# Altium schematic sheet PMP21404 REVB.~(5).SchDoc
size 431 x 279 mm; Date: Not shown in title block; ApprovedBy: Not shown in title block; CheckedBy: Not shown in title block; Author: Not shown in title block; CompanyName: Not shown in title block; Engineer: Not shown in title block; Organization: Not shown in title block; Address1: Not shown in title block; Address2: Not shown in title block; Address3: Not shown in title block; Address4: Not shown in title block; DocumentNumber: 1; Revision: Use project parameter SCH_Rev; SheetNumber: 1; SheetTotal: 1; PageSetup: Record=PageOptions¦CenterHorizontal=True¦CenterVertical=True¦PrintScale=1.00¦XCorrection=1.00¦YCorrection=1.00¦PrintKind=0¦BorderSize=5000000¦LeftOffset=0¦BottomOffset=0¦Orientation=2¦PaperLength=1000¦PaperWidth=1000¦Scale=100¦PaperSource=15¦PrintQuality=600¦MediaType=1¦DitherType=10¦PaperKind=Letter¦PrintScaleMode=1
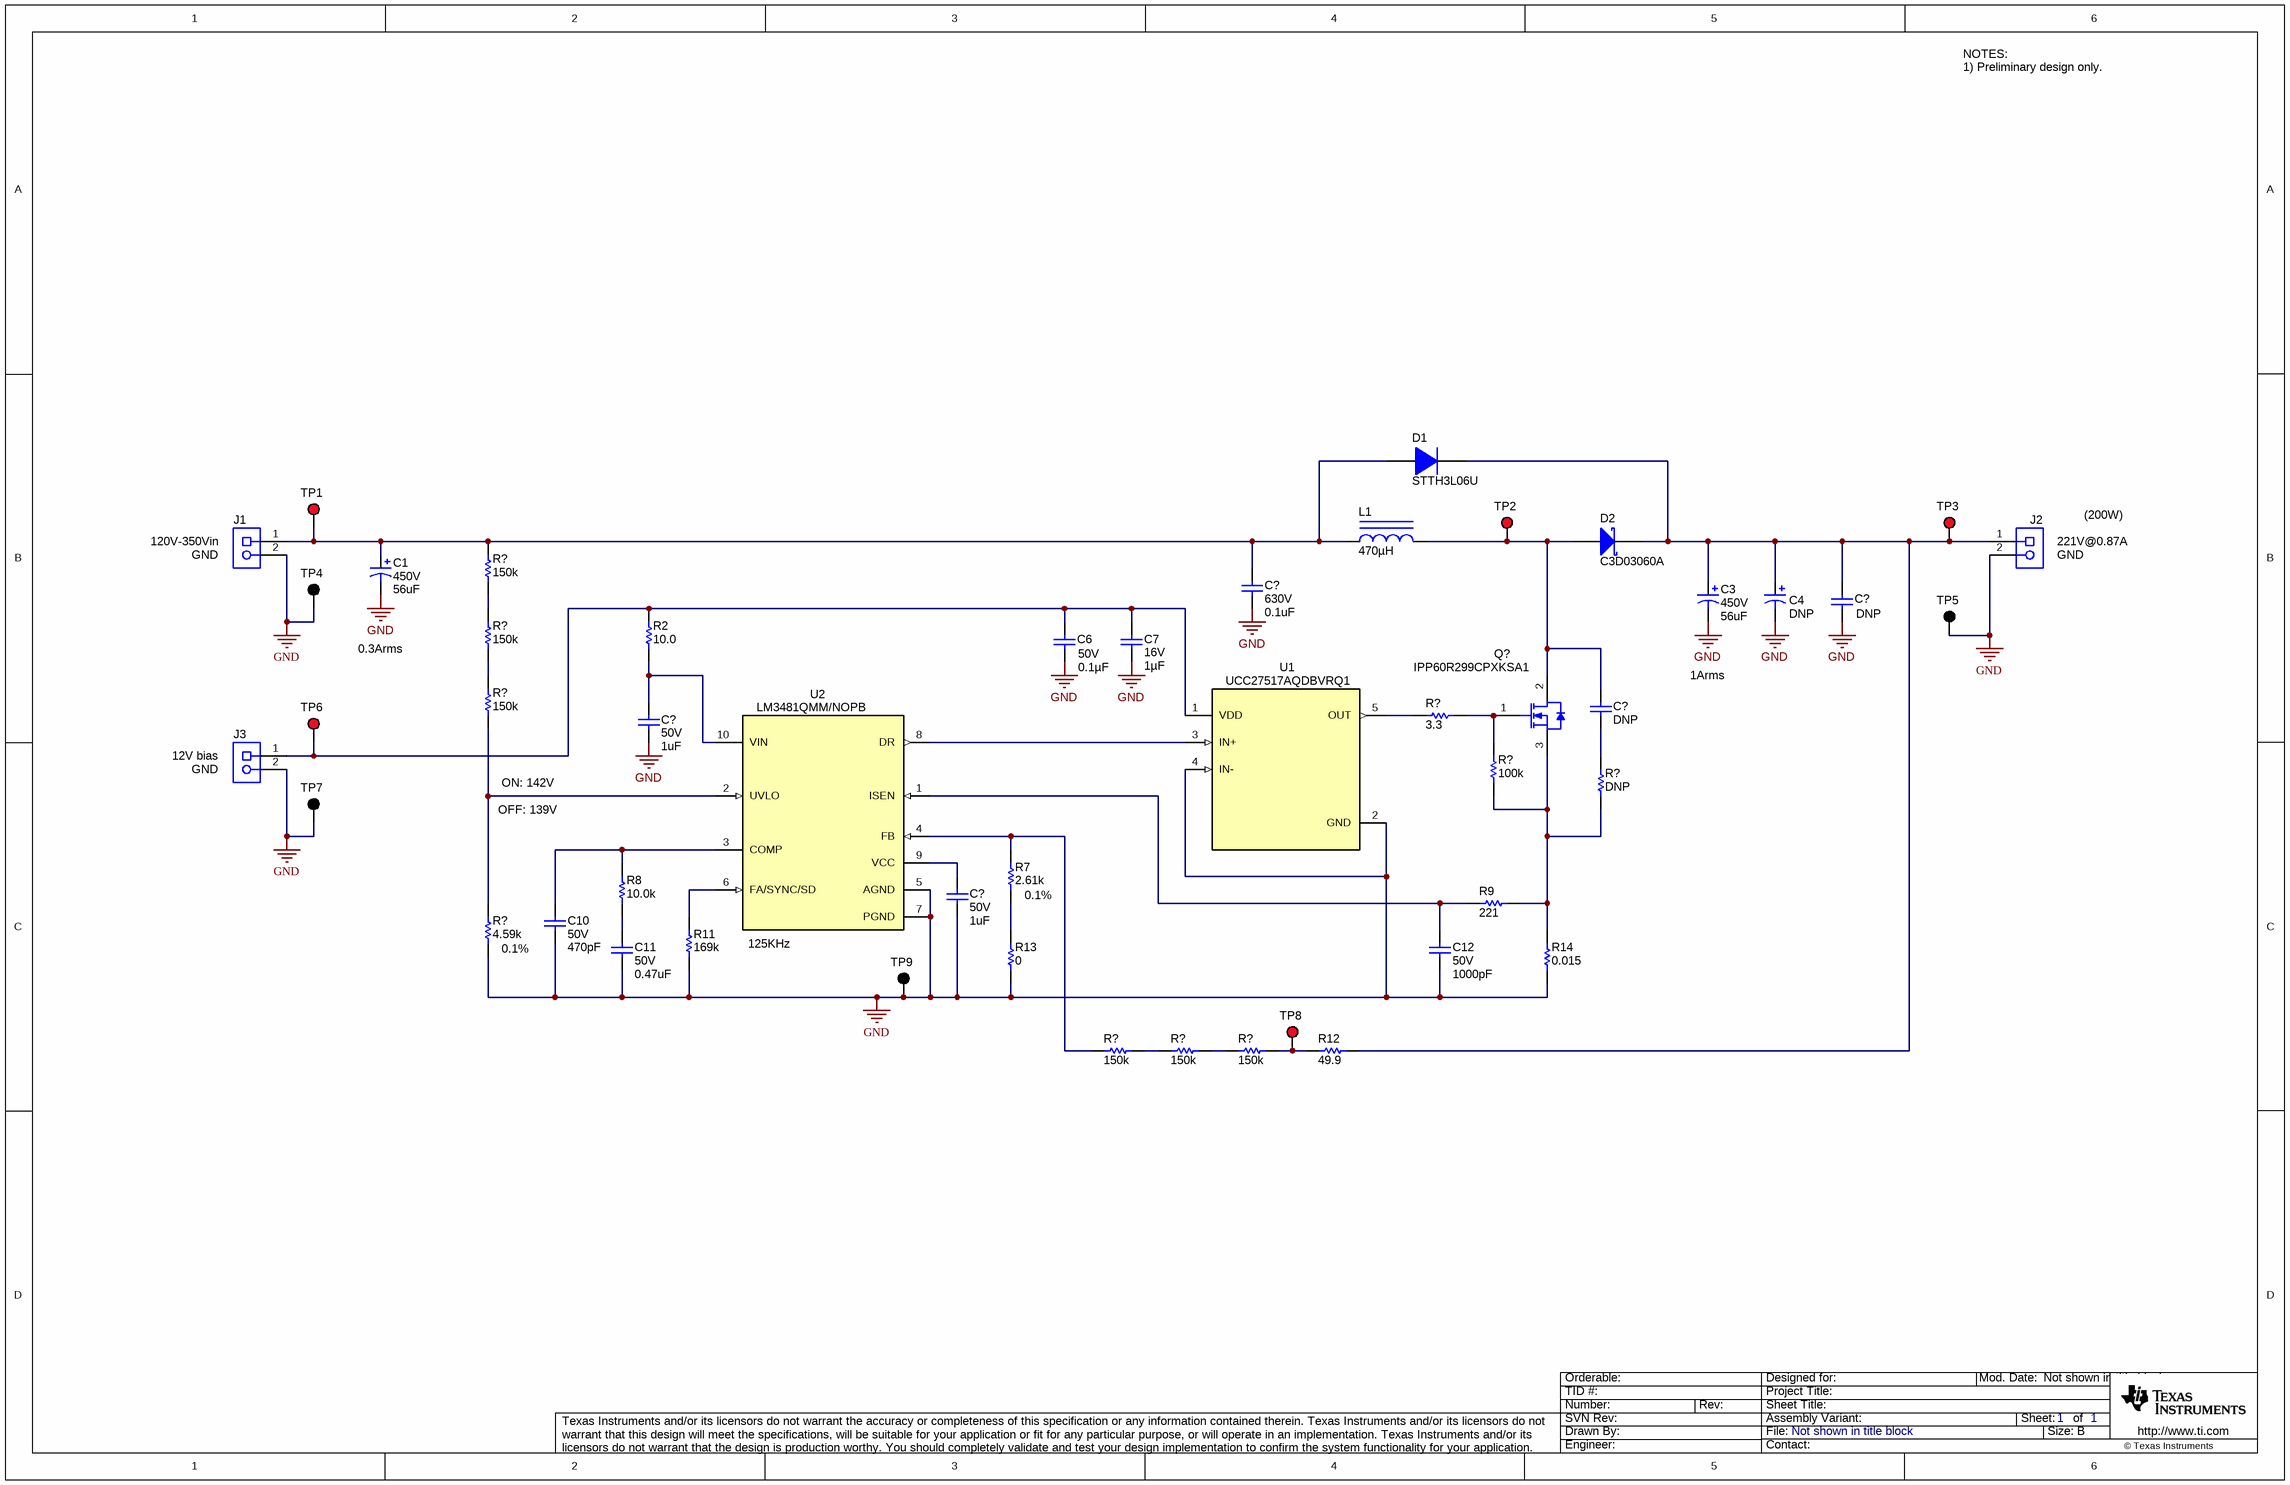
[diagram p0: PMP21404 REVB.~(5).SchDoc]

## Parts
(Parts that share a designator on the sheet are numbered #1, #2 ... from top to bottom, then left to right.)
C1  VDC_V: 450V  ValueDisplayed: 56uF  [Nichicon_2000x2500_Snap]  (hidden comment: LLS2W560MELY)
C3  VDC_V: 450V  ValueDisplayed: 56uF  [Nichicon_2000x2500_Snap]  (hidden comment: LLS2W560MELY)
C4  ValueDisplayed: DNP  [Nichicon_2000x2500_Snap]
C6  VDC_V: 50V  ValueDisplayed: 0.1µF  [0603]  (hidden comment: C0603C104K5RACAUTO)
C7  VDC_V: 16V  ValueDisplayed: 1µF  [0603]  (hidden comment: CGA3E1X7R1C105K080AC)
C10  VDC_V: 50V  ValueDisplayed: 470pF  [0603]  (hidden comment: GRM188R71H471KA01D)
C11  VDC_V: 50V  ValueDisplayed: 0.47uF  [0603]  (hidden comment: CGA3E3X7R1H474K080AB)
C12  VDC_V: 50V  ValueDisplayed: 1000pF  [0603]  (hidden comment: GRM188R71H102JA01D)
C?#1  VDC_V: 630V  ValueDisplayed: 0.1uF  [1210_200]  (hidden comment: CGA6L1X7T2J104K160AC)
C?#2  ValueDisplayed: DNP  [1210_200]  (hidden comment: CGA6L1X7T2J104K160AC)
C?#3  ValueDisplayed: DNP  [1206_190]  (hidden comment: C3216C0G2E153J160AA)
C?#4  VDC_V: 50V  ValueDisplayed: 1uF  [0805_HV]  (hidden comment: CGA4J3X7R1H105K125AB)
C?#5  VDC_V: 50V  ValueDisplayed: 1uF  [0805_HV]  (hidden comment: CGA4J3X7R1H105K125AB)
D1  STTH3L06U  [SMB]
D2  C3D03060A  [TO-220-2]
J1  Receptacle_2x1  [TERM_BLK_ED555-2DS]  (value not drawn)
J2  Receptacle_2x1  [TERM_BLK_ED555-2DS]  (value not drawn)
J3  Receptacle_2x1  [TERM_BLK_ED555-2DS]  (value not drawn)
L1  ValueDisplayed: 470µH  [Renco_RL1256-3_Pitch_750]  (hidden comment: RL-1256-3-470)
Q?  IPP60R299CPXKSA1  [TO-220AB]
R2  ValueDisplayed: 10.0  [0603]  (hidden comment: CRCW060310R0FKEA)
R7  Value1: 0.1%  ValueDisplayed: 2.61k  [0603]  (hidden comment: RG1608P-2611-B-T5)
R8  ValueDisplayed: 10.0k  [0603]  (hidden comment: CRCW060310K0FKEA)
R9  value 221  [0603L]  (hidden comment: Resistor)
R11  ValueDisplayed: 169k  [0603]  (hidden comment: CRCW0603169KFKEA)
R12  value 49.9  [0603L]  (hidden comment: Resistor)
R13  ValueDisplayed: 0  [0603]  (hidden comment: RMCF0603ZT0R00)
R14  ValueDisplayed: 0.015  [1206]  (hidden comment: WSLP1206R0150FEA)
R?#1  ValueDisplayed: 150k  [1206]  (hidden comment: CRCW1206150KFKEA)
R?#2  ValueDisplayed: 150k  [1206]  (hidden comment: CRCW1206150KFKEA)
R?#3  ValueDisplayed: 150k  [1206]  (hidden comment: CRCW1206150KFKEA)
R?#4  ValueDisplayed: 3.3  [0603]  (hidden comment: CRCW06033R30JNEA)
R?#5  ValueDisplayed: 100k  [0603]  (hidden comment: CRCW0603100KFKEA)
R?#6  ValueDisplayed: DNP  [1206]  (hidden comment: CRCW1206150KFKEA)
R?#7  Tolerance_%: 0.1%  ValueDisplayed: 4.59k  [0603]  (hidden comment: RT0603BRD074K59L)
R?#8  ValueDisplayed: 150k  [1206]  (hidden comment: CRCW1206150KFKEA)
R?#9  ValueDisplayed: 150k  [1206]  (hidden comment: CRCW1206150KFKEA)
R?#10  ValueDisplayed: 150k  [1206]  (hidden comment: CRCW1206150KFKEA)
TP1  5000  [Keystone5000]  (value not drawn)
TP2  5000  [Keystone5000]  (value not drawn)
TP3  5000  [Keystone5000]  (value not drawn)
TP4  5001  [Keystone5001]  (value not drawn)
TP5  5001  [Keystone5001]  (value not drawn)
TP6  5000  [Keystone5000]  (value not drawn)
TP7  5001  [Keystone5001]  (value not drawn)
TP8  5000  [Keystone5000]  (value not drawn)
TP9  5001  [Keystone5001]  (value not drawn)
U1  UCC27517AQDBVRQ1  [DBV0005A_N]
U2  LM3481QMM/NOPB  [DGS0010A_N]

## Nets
GND: C1.2(-) C3.2(-) C4.2(-) C6.2 C7.2 C10.2 C11.2 C12.2 C?#1.2 C?#2.2 C?#4.2 C?#5.2 J1.2 J2.2 J3.2 R11.1 R13.1 R14.1 R?#7.1 TP4.1 TP5.1 TP7.1 TP9.1 U1.2(GND) U1.4(IN-) U2.5(AGND) U2.7(PGND)
NetC1_1: C1.1(+) C?#1.1 D1.2(A) J1.1 L1.1 R?#1.2 TP1.1
NetC3_1: C3.1(+) C4.1(+) C?#2.1 D1.1(K) D2.1(K) J2.1 R12.1 TP3.1
NetC6_1: C6.1 C7.1 J3.1 R2.1 TP6.1 U1.1(VDD)
NetC10_1: C10.1 R8.2 U2.3(COMP)
NetC11_1: C11.1 R8.1
NetC12_1: C12.1 R9.2 U2.1(ISEN)
NetC?#3_1: C?#3.1 D2.2(A) L1.2 Q?.2(D) TP2.1
NetC?#3_2: C?#3.2 R?#6.1
NetC?#4_1: C?#4.1 R2.2 U2.10(VIN)
NetC?#5_1: C?#5.1 U2.9(VCC)
NetQ?_1: Q?.1(G) R?#4.2 R?#5.2
NetQ?_3: Q?.3(S) R9.1 R14.2 R?#5.1 R?#6.2
NetR7_1: R7.1 R13.2
NetR7_2: R7.2 R?#8.2 U2.4(FB)
NetR11_2: R11.2 U2.6(FA/SYNC/SD)
NetR12_2: R12.2 R?#10.1 TP8.1
NetR?#1_1: R?#1.1 R?#2.2
NetR?#2_1: R?#2.1 R?#3.2
NetR?#3_1: R?#3.1 R?#7.2 U2.2(UVLO)
NetR?#4_1: R?#4.1 U1.5(OUT)
NetR?#8_1: R?#8.1 R?#9.2
NetR?#9_1: R?#9.1 R?#10.2
NetU1_3: U1.3(IN+) U2.8(DR)

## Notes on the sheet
- NOTES:
  1) Preliminary design only.
- (near J1) 120V-350Vin
- (near J1) GND
- (near J2) 221V@0.87A
- (near J2) GND
- (200W)
- 0.3Arms
- 1Arms
- (near J3) 12V bias
- (near J3) GND
- ON: 142V
- OFF: 139V
- (near U2) 125KHz

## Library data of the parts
C1 C3 = CMP-0010119-2: CAP, AL, 56 uF, 450 V, +/- 20%, TH; Manufacturer: Nichicon; TaMin_C: -25°C; Polarized: Y; SizeAreaWB_mm2: 484; Value1: Unknown; U/M: EA; Value: 56uF; TaMax_C: 85°C; SizeZ_mm: 27; SizeX_mm: 20; Cap_Case: 20x25mm; SizeArea_mm2: 400; CompType: Capacitor; AEC Qualified: N; Cap_F: 56µF; IRMS_A: 6.1dA; AEC Category: Q200
C4 = CMP-0010119-2: CAP, AL, DNP; TaMin_C: -25°C; Polarized: Y; SizeAreaWB_mm2: 484; Value1: Unknown; U/M: EA; TaMax_C: 85°C; Tolerance_%: 20%; SizeZ_mm: 27; SizeX_mm: 20; Cap_Case: 20x25mm; SizeArea_mm2: 400; CompType: Capacitor; AEC Qualified: N; AEC Category: Q200
C6 = CMP-0079602-1: CAP, CERM, 0.1 µF, 50 V,+/- 10%, X7R, AEC-Q200 Grade 1, 0603; Manufacturer: Kemet; TaMin_C: -55°C; Polarized: N; SizeAreaWB_mm2: 4.68; U/M: EA; Value: 0.1uF; TaMax_C: 125°C; SizeZ_mm: 1; SizeX_mm: 1.6; SizeY_mm: 0.8; SizeArea_mm2: 1.28; CompType: Capacitor; AEC Qualified: Y; Cap_F: 100nF; AEC Category: Q200
C7 = CMP-0079607-1: CAP, CERM, 1 µF, 16 V,+/- 10%, X7R, AEC-Q200 Grade 1, 0603; Manufacturer: TDK; TaMin_C: -55°C; Polarized: N; SizeAreaWB_mm2: 4.68; U/M: EA; Value: 1uF; TaMax_C: 125°C; SizeZ_mm: 1; SizeX_mm: 1.6; SizeY_mm: 0.8; SizeArea_mm2: 1.28; AEC Qualified: Y; AEC Category: Q200
C10 = CMP-0007455-4: CAP, CERM, 470 pF, 50 V, +/- 10%, X7R, 0603; Manufacturer: MuRata; TaMin_C: -55°C; Polarized: N; SizeAreaWB_mm2: 4.68; Value1: Unknown; U/M: EA; Value: 470pF; TaMax_C: 125°C; SizeZ_mm: 1; SizeX_mm: 1.6; SizeY_mm: 0.8; SizeArea_mm2: 1.28; AEC Category: Q200
C11 = CMP-0007096-4: CAP, CERM, 0.47 uF, 50 V, +/- 10%, X7R, AEC-Q200 Grade 1, 0603; Manufacturer: TDK; TaMin_C: -55°C; ESR_ohm: 0.01064; Polarized: N; SizeAreaWB_mm2: 4.68; Value1: 0.01064 ohm; U/M: EA; Value: 0.47uF; TaMax_C: 125°C; SizeZ_mm: 1; SizeX_mm: 1.6; SizeY_mm: 0.8; SizeArea_mm2: 1.28; AEC Qualified: Y; Cap_F: 470nF; IRMS_A: 1.59966A; AEC Category: Q200
C12 = CMP-0007431-4: CAP, CERM, 1000 pF, 50 V, +/- 5%, X7R, 0603; Manufacturer: MuRata; TaMin_C: -55°C; Polarized: N; SizeAreaWB_mm2: 4.68; Value1: Unknown; U/M: EA; Value: 1000pF; TaMax_C: 125°C; SizeZ_mm: 1; SizeX_mm: 1.6; SizeY_mm: 0.8; SizeArea_mm2: 1.28; Cap_F: 1nF; AEC Category: Q200
C?#1 = CMP-0009140-2: CAP, CERM, 0.1 uF, 630 V, +/- 10%, X7R, AEC-Q200 Grade 1, 1210; Manufacturer: TDK; TaMin_C: -55°C; Polarized: N; SizeAreaWB_mm2: 14.7; Value1: Unknown; U/M: EA; Value: 0.1uF; TaMax_C: 125°C; SizeZ_mm: 2; SizeX_mm: 3.2; SizeY_mm: 2.5; Cap_Case: 1210; SizeArea_mm2: 8; AEC Qualified: Y; Cap_F: 100nF; AEC Grade: 1; AEC Category: Q200
C?#2 = CMP-0009140-2: CAP, CERM, DNP; Polarized: N; SizeAreaWB_mm2: 14.7; Value1: Unknown; U/M: EA; SizeZ_mm: 2; SizeX_mm: 3.2; SizeY_mm: 2.5; Cap_Case: 1210; SizeArea_mm2: 8; CompType: Capacitor; AEC Qualified: Y; AEC Grade: 1; AEC Category: Q200
C?#3 = CMP-0008644-2: CAP, CERM, DNP; Polarized: N; SizeAreaWB_mm2: 10.92; Value1: Unknown; U/M: EA; SizeZ_mm: 1.9; SizeX_mm: 3.2; SizeY_mm: 1.6; Cap_Case: 1206; SizeArea_mm2: 5.12; CompType: Capacitor; AEC Category: Q200
C?#4 C?#5 = CMP-0007976-2: CAP, CERM, 1 uF, 50 V, +/- 10%, X7R, AEC-Q200 Grade 1, 0805; Manufacturer: TDK; TaMin_C: -55°C; ESR_ohm: 8.782m; Polarized: N; SizeAreaWB_mm2: 6.75; Value1: 0.008782 ohm; U/M: EA; Value: 1uF; TaMax_C: 125°C; SizeZ_mm: 1.45; SizeX_mm: 2; SizeY_mm: 1.25; Cap_Case: 0805; SizeArea_mm2: 2.5; AEC Qualified: Y; Cap_F: 1µF; IRMS_A: 2.20488A; AEC Grade: 1; AEC Category: Q200
D1 = CMP-0077014-1: Diode, Ultrafast, 600 V, 3 A, SMB; Manufacturer: STMicroelectronics; SizeAreaWB_mm2: 44.156; Vr_V: 600V; SizeArea_mm2: 21.336; TJmax_C: 175°C; AEC Category: Q101; Value: 600V; SizeZ_mm: 2.6; Green_REACh: Incomplete; Io_A: 3A; Vf_V: 1.3V; SizeY_mm: 3.81; Green_Lifecycle: Not Set; U/M: EA; SizeX_mm: 5.6
D2 = CMP-0079543-1: Diode, Schottky, 600 V, 11 A, AEC-Q101, TH; Manufacturer: Cree; SizeAreaWB_mm2: 77.630025; Vr_V: 600V; SizeArea_mm2: 44.650025; AEC Qualified: Y; TJmax_C: 175°C; AEC Category: Q101; Value: 600V; SizeZ_mm: 20; Green_REACh: Incomplete; Io_A: 11A; SizeY_mm: 4.445; Green_Lifecycle: Active; SizeX_mm: 10.045; RJC_CperW: 3.2
J1-J3 = CMP-0074913-1: Terminal Block, 3.5mm Pitch, 2x1, TH; PartNumber: ED555/2DS; Manufacturer: On-Shore Technology; Cert_CULUS: Y; CNHeader: False; ContactFinish: Brass; CT: True; Current_A: 6A; Gender: Female; Green_Lifecycle: Active; Green_REACh: Passed; Pitch_mm: 3.5; Row_Count: 1; Shrouded: N; Voltage_V: 150V
L1 = CMP-0077831-1: Inductor, 470 µH, 4 A, 0.187 ohm, TH; Manufacturer: Renco Electronics; SizeAreaWB_mm2: 896.4036; Irms: 4A @ 40C rise; SizeArea_mm2: 780.6436; AEC Qualified: N; AEC Category: Q200; Value: 470uH; SizeZ_mm: 21.59; Imax_A: 4A; SizeY_mm: 27.94; Isat: 6A @ 5% inductance drop; DCR_ohm: 1.87d
Q? = CMP-0001176-3: MOSFET, N-CH, 600 V, 11 A, TO-220AB; Alternate Manufacturer: None; Manufacturer: Infineon Technologies; SizeZ_mm: 19.4; ChType: N; Value2: 22 nC; VdsMax_V: 600V; SizeX_mm: 10.2; SizeY_mm: 4.5; Vgs_V: 20V; Value: 600V; SizeArea_mm2: 45.9; AEC Category: Q101; IdsMax_A: 11A; SizeAreaWB_mm2: 79.3; U/M: EA; QgTyp_nC: 22
R2 = CMP-0022003-4: RES, 10.0, 1%, 0.1 W, AEC-Q200 Grade 0, 0603; Manufacturer: Vishay-Dale; Power_W: 100mW; TempCo: 100 ppm/C; Value_Code: 10R0; Value: 10.0; EIA_Code: E96; Res_ohm: 10; SizeX_mm: 1.6; SizeY_mm: 0.8; SizeZ_mm: 1; Value2: 0.1W; SizeArea_mm2: 1.28; AEC Qualified: Y; VDC_V: 75V; AEC Category: Q200; AEC Grade: 0
R7 = CMP-0023494-3: RES, 2.61 k, 0.1%, 0.1 W, 0603; Manufacturer: Susumu Co Ltd; Power_W: 100mW; TempCo: 25 ppm/C; Value_Code: 2k61; U/M: EA; Value: 2.61k; EIA_Code: E192; SizeX_mm: 1.6; SizeY_mm: 0.8; SizeZ_mm: 1; Value2: 0.1W; SizeArea_mm2: 1.28; CompType: Resistor; VDC_V: 75V; AEC Category: Q200
R8 = CMP-0021998-4: RES, 10.0 k, 1%, 0.1 W, AEC-Q200 Grade 0, 0603; Manufacturer: Vishay-Dale; Power_W: 100mW; TempCo: 100 ppm/C; Value_Code: 10k0; Value: 10.0k; EIA_Code: E96; Res_ohm: 10k; SizeX_mm: 1.6; SizeY_mm: 0.8; SizeZ_mm: 1; Value2: 0.1W; SizeArea_mm2: 1.28; AEC Qualified: Y; VDC_V: 75V; AEC Category: Q200; AEC Grade: 0
R9 = CMP-0022217-5: RES, 221, 1%, 0.1 W, AEC-Q200 Grade 0, 0603; PartNumber: CRCW0603221RFKEA; Manufacturer: Vishay-Dale; Value_Code: 221R; Power_W: 100mW; Value2: 0.1W; VDC_V: 75V; TempCo: 100 ppm/C; EIA_Code: E96; AEC Category: Q200; AEC Grade: 0; AEC Qualified: Y; SizeArea_mm2: 1.28; SizeX_mm: 1.6; SizeY_mm: 0.8; SizeZ_mm: 1
R11 = CMP-0022077-4: RES, 169 k, 1%, 0.1 W, AEC-Q200 Grade 0, 0603; Manufacturer: Vishay-Dale; Power_W: 100mW; TempCo: 100 ppm/C; Value: 169k; EIA_Code: E96; SizeX_mm: 1.6; SizeY_mm: 0.8; SizeZ_mm: 1; Value2: 0.1W; SizeArea_mm2: 1.28; AEC Qualified: Y; VDC_V: 75V; AEC Category: Q200; AEC Grade: 0
R12 = CMP-0022448-4: RES, 49.9, 1%, 0.1 W, AEC-Q200 Grade 0, 0603; PartNumber: CRCW060349R9FKEA; Manufacturer: Vishay-Dale; Value_Code: 49R9; Power_W: 100mW; Value2: 0.1W; VDC_V: 75V; TempCo: 100 ppm/C; EIA_Code: E96; AEC Category: Q200; AEC Grade: 0; AEC Qualified: Y; SizeArea_mm2: 1.28; SizeX_mm: 1.6; SizeY_mm: 0.8; SizeZ_mm: 1
R13 = CMP-0023343-3: RES, 0, 1%, 0.1 W, AEC-Q200 Grade 0, 0603; Manufacturer: Stackpole Electronics Inc; Power_W: 100mW; TempCo: ppm/C; U/M: EA; Value: 0; SizeX_mm: 1.6; SizeY_mm: 0.8; SizeZ_mm: 1; Value2: 0.1W; SizeArea_mm2: 1.28; CompType: Resistor; AEC Qualified: Y; AEC Category: Q200
R14 = CMP-0018571-2: RES, 0.015, 1%, 1 W, 1206; Manufacturer: Vishay-Dale; Power_W: 1W; TempCo: 75 ppm/C; Value_Code: R015; U/M: EA; Value: 0.015; EIA_Code: E96; SizeX_mm: 3.2; SizeY_mm: 1.6; SizeZ_mm: 1.35; SizeArea_mm2: 5.12; AEC Category: Q200
R?#1-R?#3 R?#8-R?#10 = CMP-0016639-3: RES, 150 k, 1%, 0.25 W, AEC-Q200 Grade 0, 1206; Manufacturer: Vishay-Dale; Power_W: 250mW; TempCo: 100 ppm/C; Value: 150k; EIA_Code: E96; SizeX_mm: 3.2; SizeY_mm: 1.6; SizeZ_mm: 1.35; Value2: 0.25W; SizeArea_mm2: 5.12; AEC Qualified: Y; VDC_V: 200V; AEC Category: Q200; AEC Grade: 0
R?#4 = CMP-0025805-4: RES, 3.3, 5%, 0.1 W, AEC-Q200 Grade 0, 0603; Manufacturer: Vishay-Dale; Power_W: 100mW; TempCo: 200 ppm/C; Value_Code: 3R30; Value: 3.3; EIA_Code: E24; SizeX_mm: 1.6; SizeY_mm: 0.8; SizeZ_mm: 1; Value2: 0.1W; SizeArea_mm2: 1.28; AEC Qualified: Y; VDC_V: 75V; AEC Category: Q200; AEC Grade: 0
R?#5 = CMP-0021990-4: RES, 100 k, 1%, 0.1 W, AEC-Q200 Grade 0, 0603; Manufacturer: Vishay-Dale; Power_W: 100mW; TempCo: 100 ppm/C; Value: 100k; EIA_Code: E96; SizeX_mm: 1.6; SizeY_mm: 0.8; SizeZ_mm: 1; Value2: 0.1W; SizeArea_mm2: 1.28; AEC Qualified: Y; VDC_V: 75V; AEC Category: Q200; AEC Grade: 0
R?#6 = CMP-0016639-3: RES, DNP, 1206; TempCo: 100 ppm/C; EIA_Code: E96; SizeX_mm: 3.2; SizeY_mm: 1.6; SizeZ_mm: 1.35; SizeArea_mm2: 5.12; CompType: Resistor; AEC Qualified: Y; AEC Category: Q200; AEC Grade: 0
R?#7 = CMP-0024297-2: RES, 4.59 k, 0.1%, 0.1 W, 0603; Manufacturer: Yageo America; Power_W: 100mW; TempCo: 25 ppm/C; Value_Code: 4k59; U/M: EA; Value: 4.59k; EIA_Code: E192; SizeX_mm: 1.6; SizeY_mm: 0.8; SizeZ_mm: 1; Value2: 0.1W; SizeArea_mm2: 1.28; CompType: Resistor; VDC_V: 75V; AEC Category: Q200
TP1-TP3 TP6 TP8 = CMP-0055137-1: Test Point, Miniature, Red, TH; Manufacturer: Keystone; CNHeader: FALSE; ContactFinish: Silver; CT: TRUE; Green_Lifecycle: Active; Green_REACh: Passed
TP4 TP5 TP7 TP9 = CMP-0055138-1: Test Point, Miniature, Black, TH; Manufacturer: Keystone; CNHeader: FALSE; ContactFinish: Silver; CT: TRUE; Green_Lifecycle: Active; Green_REACh: Passed
U1 = CMP-0066947-1: 4A/4A Single Channel High-speed Low-side Gate Driver, DBV0005A (SOT-23-5); Alternate Manufacturer: Texas Instruments; Green_Lifecycle: Active; SizeAreaWB_mm2: 14.82; Green_REACh: Passed; U/M: EA; SizeZ_mm: 1.45; SizeX_mm: 2.8; SizeY_mm: 2.9; SizeArea_mm2: 8.12; CompType: IC
U2 = CMP-0071928-2: High Efficiency Low-Side N-Channel Controller for Switching Regulators, AEC-Q100 Grade 1, 10-pin Mini SOIC, 1000 Reel; Manufacturer: Texas Instruments; Alternate PartNumber: LM3481QMMX/NOPB; CompType: IC; AEC Category: Q200; AEC Qualified: Y; SizeAreaWB_mm2: 23.6; SizeArea_mm2: 14.7; SizeX_mm: 4.9; SizeY_mm: 3; SizeZ_mm: 1.1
